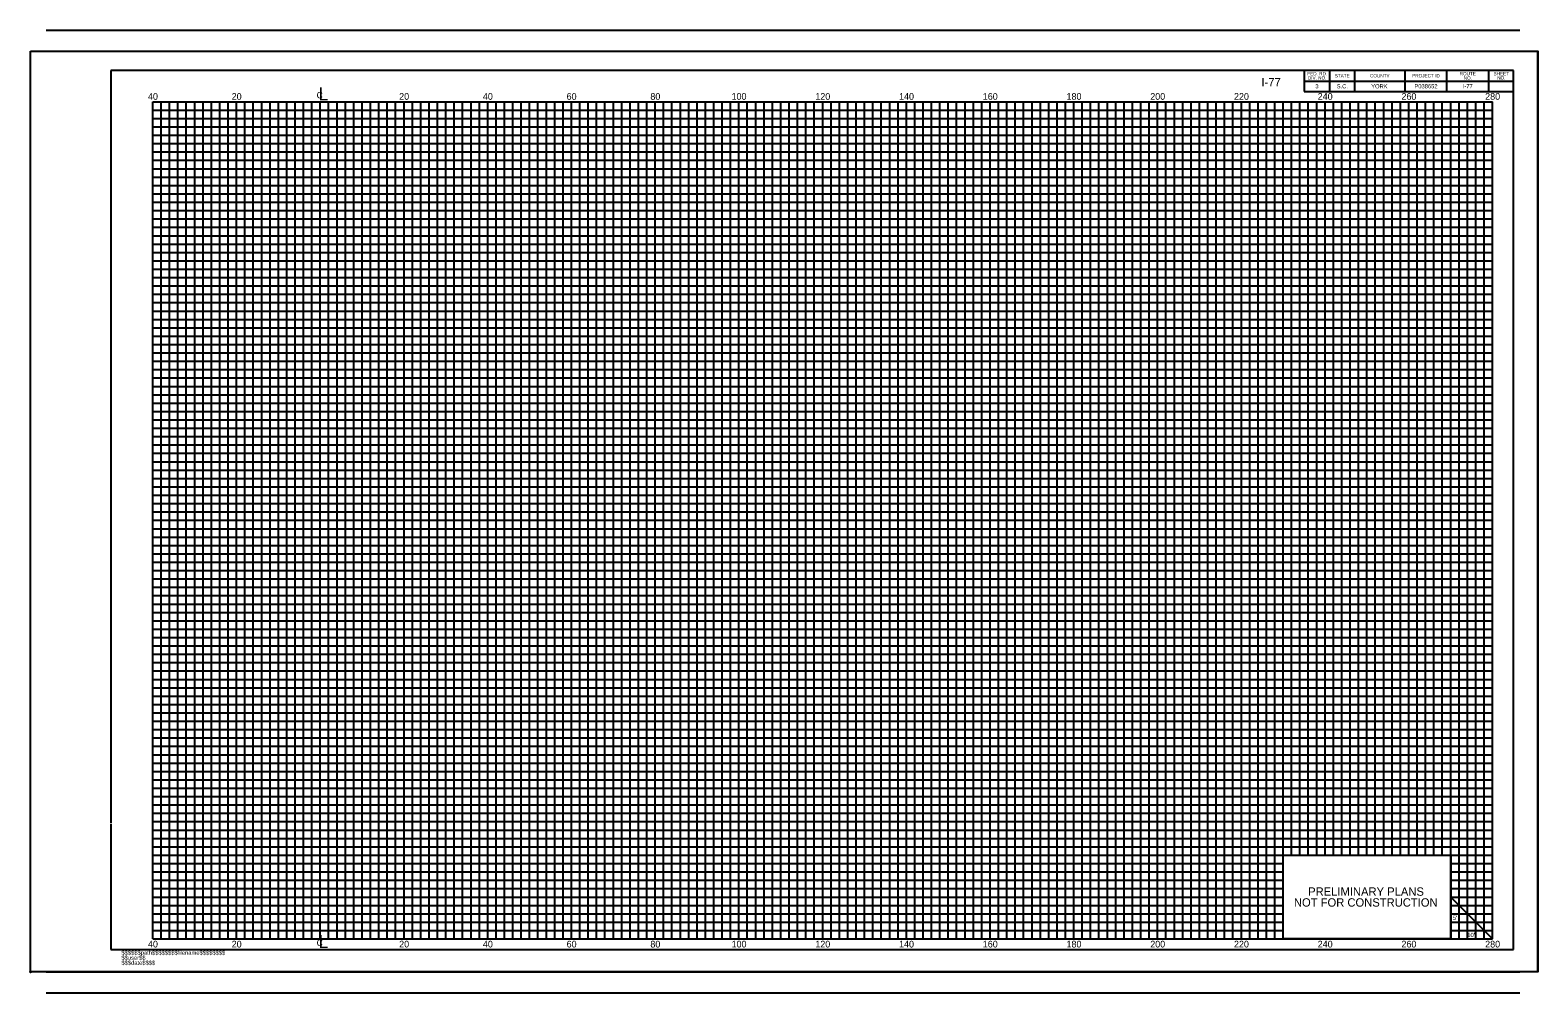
# Model space of a CAD drawing. Extents: x -15 to 165, y -6 to 109.
import ezdxf

# ---------------------------------------------------------------- set-up
doc = ezdxf.new("R2010")
doc.units = 0
for name, color, linetype in [('RD_DDB_StaTX', 7, 'Continuous'), ('RD_SHT_Bndy', 7, 'Continuous'), ('RD_SHT_ID', 7, 'Continuous'), ('RD_SHT_IplotShp', 7, 'Continuous'), ('RD_SHT_MjGrid_XS', 7, 'Continuous'), ('RD_SHT_MnGrid_XS', 7, 'Continuous'), ('RD_SHT_Snap', 7, 'Continuous'), ('RD_SHT_TX', 7, 'Continuous')]:
    doc.layers.add(name, color=color, linetype=linetype)

msp = doc.modelspace()

# ---------------------------------------------------------------- linework, layer by layer
at = {"layer": 'RD_SHT_Bndy'}
for p, q in [((-12.73, 108.55), (163.27, 108.55)), ((-12.73, 106.05), (163.27, 106.05)), ((-5, 103.72), (-5, 13.81)), ((162.51, 103.72), (-5, 103.72)), ((137.51, 103.72), (137.51, 101.22)), ((140.51, 103.72), (140.51, 101.22)), ((143.51, 103.72), (143.51, 101.22)), ((149.51, 103.72), (149.51, 101.22)), ((154.51, 103.72), (154.51, 101.22)), ((159.51, 103.72), (159.51, 101.22)), ((162.51, -1.28), (162.51, 103.72)), ((137.51, 102.47), (162.51, 102.47)), ((137.51, 101.22), (162.51, 101.22)), ((-5, 13.72), (-5, -1.28)), ((139.95, 5), (139.95, 5)), ((145, 5), (145, 5)), ((-5, -1.28), (162.51, -1.28)), ((-12.73, -3.95), (163.27, -3.95)), ((-12.73, -6.45), (163.27, -6.45))]:
    msp.add_line(p, q, dxfattribs=at)
msp.add_lwpolyline([(135, 10), (155, 10), (155, 0), (135, 0)], close=True, dxfattribs=at)
at = {"layer": 'RD_SHT_IplotShp'}
msp.add_lwpolyline([(-14.59, 106.05), (165.41, 106.05), (165.41, -3.95), (-14.59, -3.95)], close=True, dxfattribs=at)
at = {"layer": 'RD_SHT_MjGrid_XS'}
for p, q in [((0, 100), (160, 100)), ((0, 0), (0, 100)), ((5, 0), (5, 100)), ((10, 0), (10, 100)), ((15, 0), (15, 100)), ((20, 0), (20, 100)), ((25, 0), (25, 100)), ((30, 0), (30, 100)), ((35, 0), (35, 100)), ((40, 0), (40, 100)), ((45, 0), (45, 100)), ((50, 0), (50, 100)), ((55, 0), (55, 100)), ((60, 0), (60, 100)), ((65, 0), (65, 100)), ((70, 0), (70, 100)), ((75, 0), (75, 100)), ((80, 0), (80, 100)), ((85, 0), (85, 100)), ((90, 0), (90, 100)), ((95, 0), (95, 100)), ((100, 0), (100, 100)), ((105, 0), (105, 100)), ((110, 0), (110, 100)), ((115, 0), (115, 100)), ((120, 0), (120, 100)), ((125, 0), (125, 100)), ((130, 0), (130, 100)), ((135, 0), (135, 100)), ((140, 10), (140, 100)), ((145, 10), (145, 100)), ((150, 10), (150, 100)), ((155, 0), (155, 100)), ((160, 0), (160, 100)), ((0, 95), (160, 95)), ((0, 90), (160, 90)), ((0, 85), (160, 85)), ((0, 80), (160, 80)), ((0, 75), (160, 75)), ((0, 70), (160, 70)), ((0, 65), (160, 65)), ((0, 60), (160, 60)), ((0, 55), (160, 55)), ((0, 50), (160, 50)), ((0, 45), (160, 45)), ((0, 40), (160, 40)), ((0, 35), (160, 35)), ((0, 30), (160, 30)), ((0, 25), (160, 25)), ((0, 20), (160, 20)), ((0, 15), (160, 15)), ((0, 10), (160, 10)), ((0, 5), (135, 5)), ((155, 5), (160, 0)), ((155, 5), (160, 5)), ((0, 0), (160, 0))]:
    msp.add_line(p, q, dxfattribs=at)
at = {"layer": 'RD_SHT_MnGrid_XS'}
for p, q in [((1, 0), (1, 100)), ((2, 0), (2, 100)), ((3, 0), (3, 100)), ((4, 0), (4, 100)), ((6, 0), (6, 100)), ((7, 0), (7, 100)), ((8, 0), (8, 100)), ((9, 0), (9, 100)), ((11, 0), (11, 100)), ((12, 0), (12, 100)), ((13, 0), (13, 100)), ((14, 0), (14, 100)), ((16, 0), (16, 100)), ((17, 0), (17, 100)), ((18, 0), (18, 100)), ((19, 0), (19, 100)), ((21, 0), (21, 100)), ((22, 0), (22, 100)), ((23, 0), (23, 100)), ((24, 0), (24, 100)), ((26, 0), (26, 100)), ((27, 0), (27, 100)), ((28, 0), (28, 100)), ((29, 0), (29, 100)), ((31, 0), (31, 100)), ((32, 0), (32, 100)), ((33, 0), (33, 100)), ((34, 0), (34, 100)), ((36, 0), (36, 100)), ((37, 0), (37, 100)), ((38, 0), (38, 100)), ((39, 0), (39, 100)), ((41, 0), (41, 100)), ((42, 0), (42, 100)), ((43, 0), (43, 100)), ((44, 0), (44, 100)), ((46, 0), (46, 100)), ((47, 0), (47, 100)), ((48, 0), (48, 100)), ((49, 0), (49, 100)), ((51, 0), (51, 100)), ((52, 0), (52, 100)), ((53, 0), (53, 100)), ((54, 0), (54, 100)), ((56, 0), (56, 100)), ((57, 0), (57, 100)), ((58, 0), (58, 100)), ((59, 0), (59, 100)), ((61, 0), (61, 100)), ((62, 0), (62, 100)), ((63, 0), (63, 100)), ((64, 0), (64, 100)), ((66, 0), (66, 100)), ((67, 0), (67, 100)), ((68, 0), (68, 100)), ((69, 0), (69, 100)), ((71, 0), (71, 100)), ((72, 0), (72, 100)), ((73, 0), (73, 100)), ((74, 0), (74, 100)), ((76, 0), (76, 100)), ((77, 0), (77, 100)), ((78, 0), (78, 100)), ((79, 0), (79, 100)), ((81, 0), (81, 100)), ((82, 0), (82, 100)), ((83, 0), (83, 100)), ((84, 0), (84, 100)), ((86, 0), (86, 100)), ((87, 0), (87, 100)), ((88, 0), (88, 100)), ((89, 0), (89, 100)), ((91, 0), (91, 100)), ((92, 0), (92, 100)), ((93, 0), (93, 100)), ((94, 0), (94, 100)), ((96, 0), (96, 100)), ((97, 0), (97, 100)), ((98, 0), (98, 100)), ((99, 0), (99, 100)), ((101, 0), (101, 100)), ((102, 0), (102, 100)), ((103, 0), (103, 100)), ((104, 0), (104, 100)), ((106, 0), (106, 100)), ((107, 0), (107, 100)), ((108, 0), (108, 100)), ((109, 0), (109, 100)), ((111, 0), (111, 100)), ((112, 0), (112, 100)), ((113, 0), (113, 100)), ((114, 0), (114, 100)), ((116, 0), (116, 100)), ((117, 0), (117, 100)), ((118, 0), (118, 100)), ((119, 0), (119, 100)), ((121, 0), (121, 100)), ((122, 0), (122, 100)), ((123, 0), (123, 100)), ((124, 0), (124, 100)), ((126, 0), (126, 100)), ((127, 0), (127, 100)), ((128, 0), (128, 100)), ((129, 0), (129, 100)), ((131, 0), (131, 100)), ((132, 0), (132, 100)), ((133, 0), (133, 100)), ((134, 0), (134, 100)), ((136, 10), (136, 100)), ((137, 10), (137, 100)), ((138, 10), (138, 100)), ((139, 10), (139, 100)), ((141, 10), (141, 100)), ((142, 10), (142, 100)), ((143, 10), (143, 100)), ((144, 10), (144, 100)), ((146, 10), (146, 100)), ((147, 10), (147, 100)), ((148, 10), (148, 100)), ((149, 10), (149, 100)), ((151, 10), (151, 100)), ((152, 10), (152, 100)), ((153, 10), (153, 100)), ((154, 10), (154, 100)), ((156, 0), (156, 100)), ((157, 0), (157, 100)), ((158, 0), (158, 100)), ((159, 0), (159, 100)), ((0, 99), (160, 99)), ((0, 98), (160, 98)), ((0, 97), (160, 97)), ((0, 96), (160, 96)), ((0, 94), (160, 94)), ((0, 93), (160, 93)), ((0, 92), (160, 92)), ((0, 91), (160, 91)), ((0, 89), (160, 89)), ((0, 88), (160, 88)), ((0, 87), (160, 87)), ((0, 86), (160, 86)), ((0, 84), (160, 84)), ((0, 83), (160, 83)), ((0, 82), (160, 82)), ((0, 81), (160, 81)), ((0, 79), (160, 79)), ((0, 78), (160, 78)), ((0, 77), (160, 77)), ((0, 76), (160, 76)), ((0, 74), (160, 74)), ((0, 73), (160, 73)), ((0, 72), (160, 72)), ((0, 71), (160, 71)), ((0, 69), (160, 69)), ((0, 68), (160, 68)), ((0, 67), (160, 67)), ((0, 66), (160, 66)), ((0, 64), (160, 64)), ((0, 63), (160, 63)), ((0, 62), (160, 62)), ((0, 61), (160, 61)), ((0, 59), (160, 59)), ((0, 58), (160, 58)), ((0, 57), (160, 57)), ((0, 56), (160, 56)), ((0, 54), (160, 54)), ((0, 53), (160, 53)), ((0, 52), (160, 52)), ((0, 51), (160, 51)), ((0, 49), (160, 49)), ((0, 48), (160, 48)), ((0, 47), (160, 47)), ((0, 46), (160, 46)), ((0, 44), (160, 44)), ((0, 43), (160, 43)), ((0, 42), (160, 42)), ((0, 41), (160, 41)), ((0, 39), (160, 39)), ((0, 38), (160, 38)), ((0, 37), (160, 37)), ((0, 36), (160, 36)), ((0, 34), (160, 34)), ((0, 33), (160, 33)), ((0, 32), (160, 32)), ((0, 31), (160, 31)), ((0, 29), (160, 29)), ((0, 28), (160, 28)), ((0, 27), (160, 27)), ((0, 26), (160, 26)), ((0, 24), (160, 24)), ((0, 23), (160, 23)), ((0, 22), (160, 22)), ((0, 21), (160, 21)), ((0, 21), (160, 21)), ((0, 19), (160, 19)), ((0, 18), (160, 18)), ((0, 17), (160, 17)), ((0, 16), (160, 16)), ((0, 14), (160, 14)), ((0, 13), (160, 13)), ((0, 12), (160, 12)), ((0, 11), (160, 11)), ((0, 9), (135, 9)), ((0, 8), (135, 8)), ((155, 9), (160, 9)), ((155, 8), (160, 8)), ((0, 7), (135, 7)), ((0, 6), (135, 6)), ((155, 7), (160, 7)), ((155, 6), (160, 6)), ((0, 4), (135, 4)), ((155, 4), (160, 4)), ((0, 3), (135, 3)), ((0, 2), (135, 2)), ((155, 3), (160, 3)), ((155, 2), (160, 2)), ((0, 1), (135, 1)), ((155, 1), (160, 1))]:
    msp.add_line(p, q, dxfattribs=at)
at = {"layer": 'RD_SHT_Snap'}
for p, q in [((-14.59, -3.95), (-14.59, 106.05)), ((165.41, -3.95), (165.41, 106.05))]:
    msp.add_line(p, q, dxfattribs=at)
msp.add_circle((-14.59, -3.95), 0.0607, dxfattribs=at)

# ---------------------------------------------------------------- texts
at = {"layer": 'RD_DDB_StaTX'}
for s, height, p in [('40', 0.8, (-0.58, 100.23)), ('20', 0.8, (9.42, 100.23)), ('C', 0.773, (19.56, 100.4)), ('L', 1.55, (19.79, 100.16)), ('20', 0.8, (29.42, 100.23)), ('40', 0.8, (39.42, 100.23)), ('60', 0.8, (49.42, 100.23)), ('80', 0.8, (59.42, 100.23)), ('100', 0.8, (69.12, 100.23)), ('120', 0.8, (79.12, 100.23)), ('140', 0.8, (89.12, 100.23)), ('160', 0.8, (99.12, 100.23)), ('180', 0.8, (109.12, 100.23)), ('200', 0.8, (119.12, 100.23)), ('220', 0.8, (129.12, 100.23)), ('240', 0.8, (139.12, 100.23)), ('260', 0.8, (149.12, 100.23)), ('280', 0.8, (159.12, 100.23)), ('L', 1.55, (19.79, -1.09)), ('40', 0.8, (-0.58, -1.03)), ('20', 0.8, (9.42, -1.03)), ('C', 0.773, (19.56, -0.85)), ('20', 0.8, (29.42, -1.03)), ('40', 0.8, (39.42, -1.03)), ('60', 0.8, (49.42, -1.03)), ('80', 0.8, (59.42, -1.03)), ('100', 0.8, (69.12, -1.03)), ('120', 0.8, (79.12, -1.03)), ('140', 0.8, (89.12, -1.03)), ('160', 0.8, (99.12, -1.03)), ('180', 0.8, (109.12, -1.03)), ('200', 0.8, (119.12, -1.03)), ('220', 0.8, (129.12, -1.03)), ('240', 0.8, (139.12, -1.03)), ('260', 0.8, (149.12, -1.03)), ('280', 0.8, (159.12, -1.03))]:
    msp.add_text(s, height=height, dxfattribs=at).set_placement(p)
at = {"layer": 'RD_SHT_ID'}
for s, p in [('$$$$$$path$$$$$$$$filename$$$$$$$$', (-3.75, -1.9)), ('$$user$$', (-3.75, -2.5)), ('$$$date$$$$', (-3.75, -3.1))]:
    msp.add_text(s, height=0.5, rotation=360, dxfattribs=at).set_placement(p)
at = {"layer": 'RD_SHT_TX'}
for s, height, p in [('I-77', 1, (132.4, 101.83)), ('FED. RD.', 0.4, (137.88, 103.15)), ('DIV. NO.', 0.4, (137.95, 102.65)), ('STATE', 0.4, (141.15, 102.9)), ('COUNTY', 0.4, (145.37, 102.9)), ('PROJECT ID', 0.4, (150.41, 102.9)), ('ROUTE', 0.4, (156.07, 103.15)), ('NO.', 0.4, (156.56, 102.63)), ('SHEET', 0.4, (160.12, 103.15)), ('NO.', 0.4, (160.56, 102.65)), ('3', 0.5, (138.84, 101.6)), ('S.C.', 0.5, (141.39, 101.6)), ('YORK', 0.5, (145.51, 101.6)), ('P038652', 0.5, (150.67, 101.6)), ('I-77', 0.5, (156.44, 101.6)), ('PRELIMINARY PLANS', 1, (137.98, 5.15)), ('NOT FOR CONSTRUCTION', 1, (136.28, 3.85)), ("5'", 0.512, (155.26, 2.26)), ("10'", 0.512, (156.97, 0.21))]:
    msp.add_text(s, height=height, dxfattribs=at).set_placement(p)

doc.saveas('drawing.dxf')
